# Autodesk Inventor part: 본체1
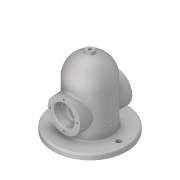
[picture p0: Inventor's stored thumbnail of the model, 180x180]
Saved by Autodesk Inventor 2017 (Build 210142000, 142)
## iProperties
Created: 2019-11
Part Number: 본체1
Material: Aluminum 6061
Document SubType Name: Modeling
Designer: 1-15-lg-1
Density: 2.7 g/cm^3
Appearance: Aluminum - Flat
Author: 1-15-lg-1
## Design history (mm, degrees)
sketch "Sketch2"
  geometry: C1 r 70 at (0, 0); 1 further point
  constraints: 1 centre point, 1 coincident
  dimensions: "d0" = 140 diameter of C1
extrude "Extrusion1" new body sketch "Sketch2" distance "d1" = 10; taper "d2" = 0 deg
sketch "Sketch3"
  geometry: L1 (10, -70)-(10, 70) reference; L2 (0, 0)-(90, 0); L3 (4.905, 40)-(4.905, -40); L4 (10, 40)-(90, 40); L5 (10, -40)-(90, -40); L6 (10, 0)-(130, 0); A1 r 40 centre (90, 0) between (90, -40) and (90, 40)
  constraints: 10 end point, 3 horizontal, 3 point on circle, 3 point on line, 1 centre point, 1 coincident, 1 midpoint, 1 vertical
  dimensions: "d4" = 80 diameter of A1; "d5" = 90 distance of L2.start L2.end; "d6" = 80 distance of L3.start L3.end; "d7" = 40 distance from line of L3.end L2
revolve "Revolution1" sketch "Sketch3" stored, may be unused: angle "d8" = 90 deg
sketch "Sketch4"
  geometry: L1 (0, 0)-(0, 50); L2 (-70, 0)-(70, 0) reference; C1 r 31 at (0, 50)
  constraints: 2 end point, 1 centre point, 1 coincident, 1 perpendicular
  dimensions: "d9" = 50 distance of L1.start L1.end; "d10" = 62 diameter of C1
extrude "Extrusion2" join sketch "Sketch4" stored distance "d11" = 100; taper "d12" = 0 deg
sketch "Sketch5"
  geometry: C1 r 31 at (0, 0) reference; C2 r 20 at (0, 0); 1 further point
  constraints: 1 centre point, 1 coincident
  dimensions: "d13" = 40 diameter of C2
extrude "Extrusion3" cut sketch "Sketch5" distance "d14" = 15; taper "d15" = 0 deg
mirror "Mirror1"
sketch "Sketch6"
  geometry: C1 r 20 at (0, 0) reference; C2 r 16.5 at (0, 0); 1 further point
  constraints: 1 centre point, 1 coincident
  dimensions: "d16" = 33 diameter of C2
extrude "Extrusion4" cut sketch "Sketch6" stored distance "d17" = 15; taper "d18" = 0 deg
sketch "Sketch8"
  geometry: L1 (0, 0)-(90, 0); L2 (0, 0)-(0, -30); L3 (0, 70)-(0, -70) reference; L4 (0, -30)-(90, -30); L5 (0, 0)-(120, 0); A1 r 30 centre (90, 0) between (90, -30) and (120, 0)
  constraints: 8 end point, 3 horizontal, 2 point on circle, 1 centre point, 1 coincident, 1 point on line
  dimensions: "d19" = 90 distance of L1.start L1.end; "d20" = 60 diameter of A1; "d21" = 30 distance of L1.start L2.end
revolve "Revolution2" sketch "Sketch8" stored, may be unused: angle "d22" = 90 deg
sketch "Sketch9" dims "d23" = 110
  geometry: L1 (0, 0)-(55, 0); C1 r 70 at (0, 0) reference; C2 r 4.5 at (55, 0)
  constraints: 2 coincident, 2 end point, 1 centre point, 1 horizontal, 1 horizontal alignment, 2 other
  dimensions: "d24" = 9 diameter of C2
extrude "Extrusion5" cut sketch "Sketch9" stored distance "d25" = 10; taper "d26" = 0 deg
mirror "Mirror2"
workplane "Work Plane1"
sketch "Sketch10"
  geometry: C1 r 7.5 at (0, 0); 1 further point
  constraints: 1 centre point, 1 coincident
  dimensions: "d28" = 15 diameter of C1
extrude "Extrusion6" join sketch "Sketch10" stored distance "d29" = 10; taper "d30" = 0 deg
sketch "Sketch11"
  geometry: C1 r 7.5 at (0, 0) reference; 1 further point
  constraints: 1 coincident
hole "Hole1" sketch "Sketch11" at (0, 0) diameter "d31" = 5.188; stored, may be unused: countersink angle "d35" = 90 deg, drill point angle "d37" = 118 deg; dims "d32" = 12, "d33" = 4, "d34" = 2, "d36" = 16
sketch "Sketch12" dims "d38" = 52
  geometry: L1 (0, 0)-(0, 26); C1 r 31 at (0, 0) reference; 2 further points
  constraints: 2 coincident, 2 end point, 1 vertical, 1 vertical alignment, 2 other
hole "Hole2" sketch "Sketch12" at (0, 26) diameter "d39" = 3.242; stored, may be unused: countersink angle "d43" = 90 deg, drill point angle "d45" = 118 deg; dims "d40" = 8, "d41" = 4, "d42" = 2, "d44" = 10
pattern_circular "Circular Pattern1" dims angle "d47" = 360 deg
mirror "Mirror3"
workplane "Work Plane2"
sketch "Sketch13"
  geometry: L1 (76.553, 15.337)-(76.553, -15.337); L2 (76.553, -15.337)-(23.447, -15.337); L3 (23.447, -15.337)-(23.447, 15.337); L4 (23.447, 15.337)-(76.553, 15.337); L5 (76.553, 0)-(23.447, 0); L6 (50, 15.337)-(50, -15.337); L7 (135, 7.5)-(135, -7.5) reference; L8 (135, 0)-(0, 0); L9 (0, 70)-(0, -70) reference; 1 further point
  constraints: 6 end point, 6 midpoint, 1 horizontal, 2 other
emboss "Emboss1" sketch "Sketch13" dims "d53" = 0.5, "d54" = 0
fillet "Fillet1" dims "d55" = 0.3
chamfer "Chamfer1" distance "d56" = 1; stored, may be unused: second distance "d57" = 2, angle "d58" = 45 deg
fillet "Fillet2" dims "d59" = 3
body "Solid1"
other parameters: "d27" = 135
